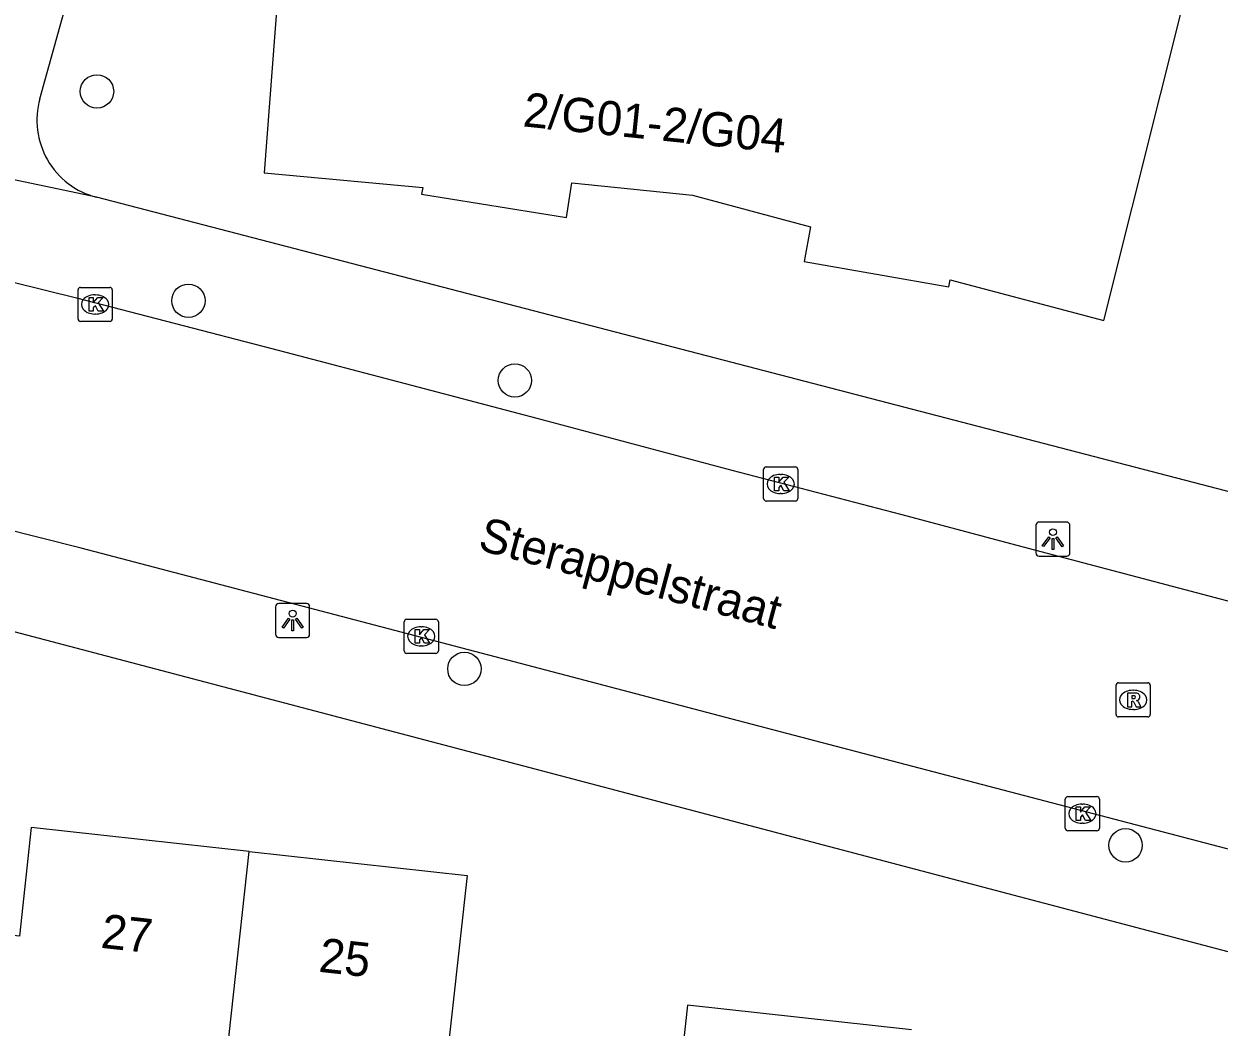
# Model space of a CAD drawing. Extents: x 162026 to 163499, y 387297 to 388169.
# Drawn here: x 162366.43 to 162401.46, y 387793.2 to 387822.59 of the extents above; entities that cross this region are included whole.
import ezdxf

# ---------------------------------------------------------------- set-up
doc = ezdxf.new("R2010")
doc.units = 0
for name, color, linetype in [('IMGEO_Boom', 7, 'Continuous'), ('IMGEO_Kolk', 7, 'Continuous'), ('IMGEO_Lichtpunt', 7, 'Continuous'), ('IMGEO_Openbare_ruimte_label', 7, 'Continuous'), ('IMGEO_Pand', 7, 'Continuous'), ('IMGEO_Pand_nummerreeks', 7, 'Continuous'), ('IMGEO_Rijbaan_lokaal_open', 7, 'Continuous'), ('IMGEO_Rioolput', 7, 'Continuous'), ('IMGEO_Voetpad_open', 7, 'Continuous')]:
    doc.layers.add(name, color=color, linetype=linetype)

msp = doc.modelspace()

# ---------------------------------------------------------------- linework, layer by layer
at = {"layer": 'IMGEO_Boom'}
for centre in [(162368.568, 387820.615), (162371.249, 387814.48), (162380.816, 387812.145), (162379.336, 387803.693), (162398.717, 387798.525)]:
    msp.add_circle(centre, 0.489, dxfattribs=at)
at = {"layer": 'IMGEO_Kolk'}
for p, q in [((162368.089, 387814.872), (162368.941, 387814.872)), ((162368.014, 387813.946), (162368.014, 387814.798)), ((162368.502, 387814.652), (162368.527, 387814.652)), ((162369.015, 387814.798), (162369.015, 387813.946)), ((162368.941, 387813.872), (162368.089, 387813.872)), ((162368.525, 387814.092), (162368.5, 387814.092)), ((162388.182, 387809.613), (162389.034, 387809.613)), ((162388.107, 387808.687), (162388.107, 387809.539)), ((162388.595, 387809.393), (162388.62, 387809.393)), ((162389.108, 387809.539), (162389.108, 387808.687)), ((162389.034, 387808.613), (162388.182, 387808.613)), ((162388.618, 387808.833), (162388.593, 387808.833)), ((162377.573, 387804.222), (162377.573, 387805.074)), ((162377.648, 387805.148), (162378.5, 387805.148)), ((162378.574, 387805.074), (162378.574, 387804.222)), ((162378.061, 387804.928), (162378.086, 387804.928)), ((162378.084, 387804.368), (162378.059, 387804.368)), ((162378.5, 387804.148), (162377.648, 387804.148)), ((162396.95, 387799.026), (162396.95, 387799.878)), ((162397.025, 387799.952), (162397.877, 387799.952)), ((162397.951, 387799.878), (162397.951, 387799.026)), ((162397.438, 387799.732), (162397.463, 387799.732)), ((162397.461, 387799.172), (162397.436, 387799.172)), ((162397.877, 387798.952), (162397.025, 387798.952))]:
    msp.add_line(p, q, dxfattribs=at)
for points in [[(162368.089, 387814.872), (162368.941, 387814.872)], [(162368.014, 387813.946), (162368.014, 387814.798)], [(162368.335, 387814.572), (162368.458, 387814.572), (162368.458, 387814.421), (162368.588, 387814.572), (162368.752, 387814.572), (162368.606, 387814.421), (162368.759, 387814.172), (162368.607, 387814.172), (162368.522, 387814.336), (162368.458, 387814.269), (162368.458, 387814.172), (162368.335, 387814.172), (162368.335, 387814.572)], [(162369.015, 387814.798), (162369.015, 387813.946)], [(162368.941, 387813.872), (162368.089, 387813.872)], [(162388.182, 387809.613), (162389.034, 387809.613)], [(162388.107, 387808.687), (162388.107, 387809.539)], [(162388.428, 387809.313), (162388.551, 387809.313), (162388.551, 387809.162), (162388.681, 387809.313), (162388.845, 387809.313), (162388.699, 387809.162), (162388.852, 387808.913), (162388.7, 387808.913), (162388.615, 387809.077), (162388.551, 387809.01), (162388.551, 387808.913), (162388.428, 387808.913), (162388.428, 387809.313)], [(162389.108, 387809.539), (162389.108, 387808.687)], [(162389.034, 387808.613), (162388.182, 387808.613)], [(162377.573, 387804.222), (162377.573, 387805.074)], [(162377.648, 387805.148), (162378.5, 387805.148)], [(162378.574, 387805.074), (162378.574, 387804.222)], [(162377.894, 387804.848), (162378.017, 387804.848), (162378.017, 387804.697), (162378.147, 387804.848), (162378.311, 387804.848), (162378.165, 387804.697), (162378.318, 387804.448), (162378.166, 387804.448), (162378.081, 387804.612), (162378.017, 387804.545), (162378.017, 387804.448), (162377.894, 387804.448), (162377.894, 387804.848)], [(162378.5, 387804.148), (162377.648, 387804.148)], [(162396.95, 387799.026), (162396.95, 387799.878)], [(162397.025, 387799.952), (162397.877, 387799.952)], [(162397.951, 387799.878), (162397.951, 387799.026)], [(162397.271, 387799.652), (162397.394, 387799.652), (162397.394, 387799.501), (162397.524, 387799.652), (162397.688, 387799.652), (162397.542, 387799.501), (162397.695, 387799.252), (162397.543, 387799.252), (162397.458, 387799.416), (162397.394, 387799.349), (162397.394, 387799.252), (162397.271, 387799.252), (162397.271, 387799.652)], [(162397.877, 387798.952), (162397.025, 387798.952)]]:
    msp.add_lwpolyline(points, dxfattribs=at)
for centre, start, end in [((162368.091, 387814.796), 91.552, 178.448), ((162368.091, 387814.796), 91.552, 178.448), ((162368.939, 387814.796), 1.552, 88.448), ((162368.939, 387814.796), 1.552, 88.448), ((162368.091, 387813.948), 181.552, 268.448), ((162368.091, 387813.948), 181.552, 268.448), ((162368.939, 387813.948), 271.552, 358.448), ((162368.939, 387813.948), 271.552, 358.448), ((162388.184, 387809.537), 91.552, 178.448), ((162388.184, 387809.537), 91.552, 178.448), ((162389.032, 387809.537), 1.552, 88.448), ((162389.032, 387809.537), 1.552, 88.448), ((162388.184, 387808.689), 181.552, 268.448), ((162388.184, 387808.689), 181.552, 268.448), ((162389.032, 387808.689), 271.552, 358.448), ((162389.032, 387808.689), 271.552, 358.448), ((162377.65, 387805.072), 91.552, 178.448), ((162377.65, 387805.072), 91.552, 178.448), ((162378.498, 387805.072), 1.552, 88.448), ((162378.498, 387805.072), 1.552, 88.448), ((162377.65, 387804.224), 181.552, 268.448), ((162377.65, 387804.224), 181.552, 268.448), ((162378.498, 387804.224), 271.552, 358.448), ((162378.498, 387804.224), 271.552, 358.448), ((162397.027, 387799.876), 91.552, 178.448), ((162397.027, 387799.876), 91.552, 178.448), ((162397.875, 387799.876), 1.552, 88.448), ((162397.875, 387799.876), 1.552, 88.448), ((162397.027, 387799.028), 181.552, 268.448), ((162397.027, 387799.028), 181.552, 268.448), ((162397.875, 387799.028), 271.552, 358.448), ((162397.875, 387799.028), 271.552, 358.448)]:
    msp.add_arc(centre, 0.0765, start, end, dxfattribs=at)
for centre, major_axis, ratio, start_param, end_param in [((162368.501, 387814.372), (-0.387, 0.002), 0.722429, 4.712389, 7.853982), ((162368.526, 387814.372), (-0.39, 0.002), 0.717154, 1.570796, 4.712389), ((162388.594, 387809.113), (-0.387, 0.002), 0.722429, 4.712389, 7.853982), ((162388.619, 387809.113), (-0.39, 0.002), 0.717154, 1.570796, 4.712389), ((162378.06, 387804.648), (-0.387, 0.002), 0.722429, 4.712389, 7.853982), ((162378.085, 387804.648), (-0.39, 0.002), 0.717154, 1.570796, 4.712389), ((162397.437, 387799.452), (-0.387, 0.002), 0.722429, 4.712389, 7.853982), ((162397.462, 387799.452), (-0.39, 0.002), 0.717154, 1.570796, 4.712389)]:
    msp.add_ellipse(centre, major_axis=major_axis, ratio=ratio, start_param=start_param, end_param=end_param, dxfattribs=at)
at = {"layer": 'IMGEO_Lichtpunt'}
for p, q in [((162396.089, 387807.902), (162396.089, 387807.095)), ((162396.089, 387807.902), (162396.089, 387807.095)), ((162396.991, 387807.997), (162396.183, 387807.997)), ((162396.991, 387807.997), (162396.183, 387807.997)), ((162397.085, 387807.095), (162397.085, 387807.902)), ((162397.085, 387807.095), (162397.085, 387807.902)), ((162396.183, 387807.001), (162396.991, 387807.001)), ((162396.183, 387807.001), (162396.991, 387807.001)), ((162373.805, 387805.515), (162373.805, 387804.708)), ((162373.805, 387805.515), (162373.805, 387804.708)), ((162374.707, 387805.61), (162373.899, 387805.61)), ((162374.707, 387805.61), (162373.899, 387805.61)), ((162374.801, 387804.708), (162374.801, 387805.515)), ((162374.801, 387804.708), (162374.801, 387805.515)), ((162373.899, 387804.614), (162374.707, 387804.614)), ((162373.899, 387804.614), (162374.707, 387804.614))]:
    msp.add_line(p, q, dxfattribs=at)
for points in [[(162396.463, 387807.566), (162396.502, 387807.538), (162396.314, 387807.276), (162396.276, 387807.303), (162396.463, 387807.566)], [(162396.565, 387807.518), (162396.612, 387807.518), (162396.612, 387807.196), (162396.565, 387807.196), (162396.565, 387807.518)], [(162396.675, 387807.538), (162396.713, 387807.565), (162396.9, 387807.303), (162396.861, 387807.275), (162396.675, 387807.538)], [(162374.179, 387805.179), (162374.218, 387805.151), (162374.03, 387804.889), (162373.992, 387804.916), (162374.179, 387805.179)], [(162374.281, 387805.131), (162374.328, 387805.131), (162374.328, 387804.809), (162374.281, 387804.809), (162374.281, 387805.131)], [(162374.391, 387805.151), (162374.429, 387805.178), (162374.616, 387804.916), (162374.577, 387804.888), (162374.391, 387805.151)]]:
    msp.add_lwpolyline(points, dxfattribs=at)
for centre in [(162396.588, 387807.7), (162374.304, 387805.313)]:
    msp.add_circle(centre, 0.0994, dxfattribs=at)
for centre, start, end in [((162396.183, 387807.902), 90, 180), ((162396.183, 387807.902), 90, 180), ((162396.991, 387807.902), 0, 90), ((162396.991, 387807.902), 0, 90), ((162396.183, 387807.095), 180, 270), ((162396.183, 387807.095), 180, 270), ((162396.991, 387807.095), 270, 0), ((162396.991, 387807.095), 270, 360), ((162373.899, 387805.515), 90, 180), ((162373.899, 387805.515), 90, 180), ((162374.707, 387805.515), 0, 90), ((162374.707, 387805.515), 0, 90), ((162373.899, 387804.708), 180, 270), ((162373.899, 387804.708), 180, 270), ((162374.707, 387804.708), 270, 0), ((162374.707, 387804.708), 270, 360)]:
    msp.add_arc(centre, 0.0946, start, end, dxfattribs=at)
at = {"layer": 'IMGEO_Pand'}
for points in [[(162374.017, 387825.414), (162373.472, 387818.228), (162378.118, 387817.803), (162378.079, 387817.606), (162382.33, 387816.916), (162382.489, 387817.935), (162386.02, 387817.572), (162389.478, 387816.648), (162389.299, 387815.628), (162393.537, 387814.893), (162393.571, 387815.091), (162398.075, 387813.9)], [(162398.075, 387813.9), (162400.572, 387823.844)], [(162373.032, 387798.344), (162366.643, 387799.047), (162366.293, 387795.865), (162362.888, 387796.24)], [(162372.109, 387789.947), (162373.032, 387798.344)], [(162373.032, 387798.344), (162379.418, 387797.641), (162378.758, 387791.637), (162382.158, 387791.263)], [(162392.44, 387793.118), (162385.881, 387793.839), (162385.557, 387790.89), (162382.158, 387791.263)]]:
    msp.add_lwpolyline(points, dxfattribs=at)
at = {"layer": 'IMGEO_Rijbaan_lokaal_open'}
for points in [[(162362.667, 387815.86), (162363.334, 387815.705), (162367.97, 387814.57), (162373.697, 387813.078), (162377.782, 387812.01), (162381.46, 387811.044), (162387.179, 387809.517), (162392.118, 387808.232), (162395.53, 387807.317), (162419.595, 387800.972), (162435.475, 387796.8)], [(162434.534, 387789.716), (162425.554, 387792.156), (162419.266, 387793.821), (162406.505, 387797.167), (162399.824, 387798.914), (162387.371, 387802.176), (162380.427, 387804), (162368.103, 387807.231), (162363.251, 387808.448), (162361.204, 387808.902)]]:
    msp.add_lwpolyline(points, dxfattribs=at)
at = {"layer": 'IMGEO_Rioolput'}
for p, q in [((162398.513, 387803.287), (162399.365, 387803.287)), ((162398.438, 387802.361), (162398.438, 387803.213)), ((162398.926, 387803.067), (162398.951, 387803.067)), ((162399.439, 387803.213), (162399.439, 387802.361)), ((162399.365, 387802.287), (162398.513, 387802.287)), ((162398.949, 387802.507), (162398.924, 387802.507))]:
    msp.add_line(p, q, dxfattribs=at)
for points in [[(162398.513, 387803.287), (162399.365, 387803.287)], [(162398.438, 387802.361), (162398.438, 387803.213)], [(162399.027, 387802.985), (162398.775, 387802.987), (162398.775, 387802.587)], [(162398.953, 387802.906), (162398.899, 387802.906), (162398.899, 387802.825)], [(162399.439, 387803.213), (162399.439, 387802.361)], [(162398.775, 387802.587), (162398.899, 387802.587), (162398.899, 387802.749), (162398.91, 387802.749)], [(162398.899, 387802.825), (162398.951, 387802.825)], [(162398.957, 387802.72), (162399.028, 387802.587), (162399.168, 387802.587), (162399.103, 387802.713)], [(162399.365, 387802.287), (162398.513, 387802.287)]]:
    msp.add_lwpolyline(points, dxfattribs=at)
for centre, radius, start, end in [((162398.515, 387803.211), 0.0765, 91.552, 178.448), ((162398.515, 387803.211), 0.0765, 91.552, 178.448), ((162399.363, 387803.211), 0.0765, 1.552, 88.448), ((162399.363, 387803.211), 0.0765, 1.552, 88.448), ((162398.959, 387802.81), 0.0964, 77.0061, 93.1865), ((162399.026, 387802.875), 0.109, 350.3612, 89.416), ((162398.909, 387802.696), 0.0533, 26.0293, 88.6989), ((162398.935, 387803.014), 0.19, 274.7715, 282.9687), ((162398.973, 387802.867), 0.0378, 276.6634, 79.6772), ((162399.024, 387802.875), 0.112, 277.5842, 350.9817), ((162399.008, 387802.66), 0.108, 29.5134, 73.7905), ((162398.515, 387802.363), 0.0765, 181.552, 268.448), ((162398.515, 387802.363), 0.0765, 181.552, 268.448), ((162399.363, 387802.363), 0.0765, 271.552, 358.448), ((162399.363, 387802.363), 0.0765, 271.552, 358.448)]:
    msp.add_arc(centre, radius, start, end, dxfattribs=at)
for centre, major_axis, ratio, start_param, end_param in [((162398.925, 387802.787), (-0.387, 0.002), 0.722429, 4.712389, 7.853982), ((162398.95, 387802.787), (-0.39, 0.002), 0.717154, 1.570796, 4.712389)]:
    msp.add_ellipse(centre, major_axis=major_axis, ratio=ratio, start_param=start_param, end_param=end_param, dxfattribs=at)
at = {"layer": 'IMGEO_Voetpad_open'}
for points in [[(162366.892, 387820.401), (162369.065, 387828.195), (162371.305, 387836.232)], [(162368.558, 387817.511), (162363.204, 387818.638)], [(162402.137, 387808.789), (162368.558, 387817.511)], [(162302.745, 387811.357), (162304.731, 387812.656), (162306.963, 387812.388), (162360.929, 387806.153), (162438.185, 387785.808), (162484.708, 387780.319)]]:
    msp.add_lwpolyline(points, dxfattribs=at)
msp.add_arc((162369.145, 387819.775), 2.339, 164.468, 255.4564, dxfattribs=at)

# ---------------------------------------------------------------- texts
at = {"layer": 'IMGEO_Openbare_ruimte_label'}
msp.add_text('Sterappelstraat', height=1, rotation=345.0464, dxfattribs=at).set_placement((162379.699, 387807.194))
at = {"layer": 'IMGEO_Pand_nummerreeks'}
for s, rotation, p in [('2/G01-2/G04', 354.1304, (162381.029, 387819.593)), ('27', 353.7204, (162368.656, 387795.526)), ('25', 353.7194, (162375.044, 387794.823))]:
    msp.add_text(s, height=1, rotation=rotation, dxfattribs=at).set_placement(p)

doc.saveas('drawing.dxf')
